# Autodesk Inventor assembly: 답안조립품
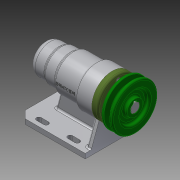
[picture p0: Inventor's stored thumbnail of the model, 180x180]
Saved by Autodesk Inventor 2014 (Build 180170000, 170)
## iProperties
Created: 2017-09
Part Number: 답안조립품
Document SubType Name: Assembly
Designer: user
Author: user
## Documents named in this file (12)
- C:\Users\user\Desktop\470907V1001\답안조립품.iam
- C:\Users\user\Desktop\470907V1001\본체.ipt
- C:\Users\user\Desktop\470907V1001\커버.ipt
- C:\Users\user\Desktop\470907V1001\볼트 M4 x 12.ipt
- C:\Users\user\Desktop\470907V1001\베어링 6004.ipt
- C:\Users\user\Desktop\470907V1001\축.ipt
- C:\Users\user\Desktop\470907V1001\오일 실 20x35x7.ipt
- C:\Users\user\Desktop\470907V1001\어댑터슬리브.ipt
- C:\Users\user\Desktop\470907V1001\베어링 51202.ipt
- C:\Users\user\Desktop\470907V1001\키 5 x 5 x 16.ipt
- C:\Users\user\Desktop\470907V1001\V벨트풀리.ipt
- C:\Users\user\Desktop\470907V1001\멈춤나사 M3x8.ipt
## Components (1 placed, 1 different names)
1. V벨트풀리:1
